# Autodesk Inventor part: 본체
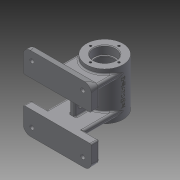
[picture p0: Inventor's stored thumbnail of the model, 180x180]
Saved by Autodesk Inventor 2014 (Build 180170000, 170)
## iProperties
Created: 2016-07
Part Number: 본체
Material: Generic
Document SubType Name: Modeling
Designer: user
Density: 1 g/cm^3
Appearance: Default
Author: user
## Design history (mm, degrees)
sketch "Sketch1"
  geometry: C1 r 27 at (0, 0); 1 further point
  constraints: 1 centre point, 1 coincident
  dimensions: "d0" = 54 diameter of C1
extrude "Extrusion1" new body sketch "Sketch1" stored distance "d1" = 70; taper "d2" = 0 deg
workplane "Work Plane1"
sketch "Sketch2"
  geometry: L1 (27, -35)-(27, 35) reference; L2 (27, 35)-(-27, 35) reference; L3 (-27, -35)-(-27, 35) reference; L4 (-27, -35)-(27, -35) reference; L5 (0, 55)-(50, 55); L6 (50, 55)-(50, 20); L7 (50, 20)-(0, 20); L8 (-50, 20)-(0, 20); L9 (-50, 55)-(-50, 20); L10 (0, 55)-(-50, 55); 1 further point
  constraints: 12 end point, 1 perpendicular
  dimensions: "d5" = 50 distance of L5.start L5.end; "d6" = 35 distance of L5.end L6.end; "d7" = 50 distance of L6.end L7.end; "d8" = 90 deg angle of L6 L5; "d9" = 90 deg angle of L7 L6; "d10" = 55 distance from line of L4 L6.end; "d12" = 23 distance from line of L1 L6.end; "d13" = 50 distance of L5.start L9.start; "d14" = 50 distance of L8.start L7.end; "d15" = 35 distance of L9.start L8.start; "d16" = 23 distance from line of L3 L9.start
extrude "Extrusion2" join sketch "Sketch2" distance "d17" = 12; taper "d18" = 0 deg
mirror "Mirror1"
sketch "Sketch3"
  geometry: L1 (50, -20)-(-50, -20) reference; L2 (-27, -28)-(27, -28); L3 (27, -28)-(27, -20); L4 (27, -20)-(-27, -20); L5 (-27, -20)-(-27, -28); 3 further points
  constraints: 8 end point, 3 midpoint, 2 parallel, 1 horizontal, 1 perpendicular, 1 vertical alignment
  dimensions: "d19" = 54 distance of L4.end L3.end; "d20" = 8 distance of L3.end L2.end
extrude "Extrusion3" join sketch "Sketch3" stored distance "d21" = 12; taper "d22" = 0 deg
mirror "Mirror2"
workplane "Work Plane2"
sketch "Sketch4"
  geometry: L1 (4, 20)-(-4, 20); L2 (-4, 20)-(-4, -20); L3 (-4, -20)-(4, -20); L4 (4, -20)-(4, 20); 3 further points
  constraints: 8 end point, 2 midpoint, 2 parallel, 1 horizontal, 1 horizontal alignment, 1 perpendicular, 1 vertical alignment
  dimensions: "d24" = 8 distance of L3.end L2.end; "d25" = 40 distance of L2.end L1.end
extrude "Extrusion4" join sketch "Sketch4" stored distance "d26" = 10; taper "d27" = 0 deg
sketch "Sketch5"
  geometry: L1 (0, 0)-(0, 21.298) reference; L2 (40, 21.298)-(40, 0) reference; L3 (12, 13.5)-(28, 13.5); L4 (12, 6.5)-(28, 6.5); L5 (40, -22)-(75, -22) reference; A1 r 3.5 centre (12, 10) between (12, 13.5) and (12, 6.5); A2 r 3.5 centre (28, 10) between (28, 6.5) and (28, 13.5); 1 further point
  constraints: 4 end point, 4 point on circle, 2 centre point, 2 tangent
  dimensions: "d29" = 7 diameter of A1; "d30" = 7 diameter of A2; "d31" = 23 dimension on A2 A1; "d32" = 12 distance from line of L2 A2.centre; "d34" = 12 distance from line of L1 A1.centre; "d35" = 16 distance of L3.start L3.end; "d36" = 16 distance of L4.start L4.end; "d114" = 32 distance from line of L5 A2.centre
extrude "Extrusion5" cut sketch "Sketch5" stored distance "d37" = 10; taper "d38" = 0 deg
sketch "Sketch6"
  geometry: L1 (-50, -20)-(-50, -55) reference; L2 (-50, -55)-(50, -55) reference; 2 further points
  dimensions: "d39" = 12.5 distance from line of point (-37.5, -42.5) L1; "d40" = 12.5 distance from line of point (-37.5, -42.5) L2
hole "Hole1" sketch "Sketch6" at (-37.5, -42.5) diameter "d41" = 6; stored, may be unused: countersink angle "d45" = 90 deg, drill point angle "d47" = 0 deg; dims "d42" = 6, "d43" = 10, "d44" = 4, "d46" = 12
mirror "Mirror3"
mirror "Mirror4"
sketch "Sketch7"
  geometry: C1 r 27 at (0, 0) reference; C2 r 16 at (0, 0)
  constraints: 1 centre point, 1 coincident
  dimensions: "d48" = 32 diameter of C2
extrude "Extrusion6" cut sketch "Sketch7" distance "d49" = 12; taper "d50" = 0 deg
sketch "Sketch8"
  geometry: C1 r 16 at (0, 0) reference; C2 r 14 at (0, 0)
  constraints: 1 centre point, 1 coincident
  dimensions: "d51" = 28 diameter of C2
extrude "Extrusion7" cut sketch "Sketch8" distance "d52" = 2; taper "d53" = 0 deg
sketch "Sketch9"
  geometry: C1 r 14 at (0, 0) reference; C2 r 22 at (0, 0)
  constraints: 1 centre point, 1 coincident
  dimensions: "d54" = 44 diameter of C2
extrude "Extrusion8" cut sketch "Sketch9" distance "d55" = 42; taper "d56" = 0 deg
mirror "Mirror5"
sketch "Sketch10"
  geometry: C1 r 16 at (0, 0) reference; 1 further point
  dimensions: "d57" = 21 distance of C1.centre point (0, 21)
hole "Hole2" sketch "Sketch10" at (0, 21) diameter "d58" = 3.242; stored, may be unused: countersink angle "d62" = 90 deg, drill point angle "d64" = 118 deg; dims "d59" = 8, "d60" = 10, "d61" = 4, "d63" = 10
pattern_circular "Circular Pattern1" dims angle "d66" = 360 deg
mirror "Mirror6"
workplane "Work Plane3"
sketch "Sketch11"
  geometry: L1 (27, 35)-(-27, 35) reference; L2 (27, -35)-(27, 35) reference; L3 (-20.368, 20.739)-(-20.368, -20.739); L4 (-20.368, -20.739)-(20.368, -20.739); L5 (20.368, -20.739)-(20.368, 20.739); L6 (20.368, 20.739)-(-20.368, 20.739); 4 further points
  constraints: 2 midpoint, 1 horizontal alignment, 1 vertical alignment, 2 other
  dimensions: "d69" = 35 distance from line of L1 point (0, 0); "d70" = 27 distance from line of point (0, 0) L2
emboss "Emboss1" sketch "Sketch11" dims "d71" = 0.5, "d72" = 0
workplane "Work Plane4"
sketch "Sketch12"
  geometry: L1 (27, 35)-(-27, 35) reference; C1 r 5 at (0, 13); 1 further point
  constraints: 1 centre point
  dimensions: "d75" = 10 diameter of C1; "d76" = 22 distance from line of L1 C1.centre
extrude "Extrusion9" join sketch "Sketch12" stored distance "d77" = 42; taper "d78" = 0 deg
sketch "Sketch13"
  geometry: C1 r 5 at (0, 0) reference; 2 further points
  constraints: 1 coincident
hole "Hole3" sketch "Sketch13" at (0, 0) diameter "d79" = 5.188; stored, may be unused: countersink angle "d83" = 90 deg, drill point angle "d85" = 0 deg; dims "d80" = 9, "d81" = 10, "d82" = 4, "d84" = 9
sketch "Sketch14"
  geometry: L1 (0, 0)-(0, -81.093); L2 (0, 0)-(-15.898, -25.441)
  constraints: 4 end point, 1 vertical
  dimensions: "d86" = 32 deg angle of L2 L1; "d87" = 30 distance of L1.start L2.end
workplane "Work Plane5"
sketch "Sketch15"
  geometry: C1 r 6 at (0, 0); 1 further point
  constraints: 1 centre point, 1 coincident
  dimensions: "d88" = 12 diameter of C1
extrude "Extrusion10" join sketch "Sketch15" stored distance "d89" = 42; taper "d90" = 0 deg
sketch "Sketch16"
  geometry: C1 r 6 at (0, 0) reference; 1 further point
  constraints: 1 coincident
hole "Hole4" sketch "Sketch16" at (0, 0) diameter "d91" = 5.188; stored, may be unused: countersink angle "d95" = 90 deg, drill point angle "d97" = 0 deg; dims "d92" = 9, "d93" = 10, "d94" = 4, "d96" = 9
fillet "Fillet3" dims "d102" = 2
fillet "Fillet4" dims "d103" = 2
fillet "Fillet5" dims "d104" = 3
fillet "Fillet6" dims "d105" = 2
fillet "Fillet8" dims "d107" = 2
fillet "Fillet9" dims "d108" = 2
chamfer "Chamfer1" distance "d109" = 1; stored, may be unused: second distance "d110" = 2, angle "d111" = 45 deg
fillet "Fillet10" dims "d112" = 0.3
fillet "Fillet11" dims "d113" = 3
feature "FaceDraft3" dims angle "d115" = -20 deg
feature "FaceDraft5" dims angle "d121" = -20 deg
fillet "Fillet15" dims "d122" = 10, "d123" = 5
mirror "Mirror9"
mirror "Mirror10"
fillet "Fillet16" dims "d124" = 2
body "Solid1"
other parameters: "d23" = -48, "d68" = 27
